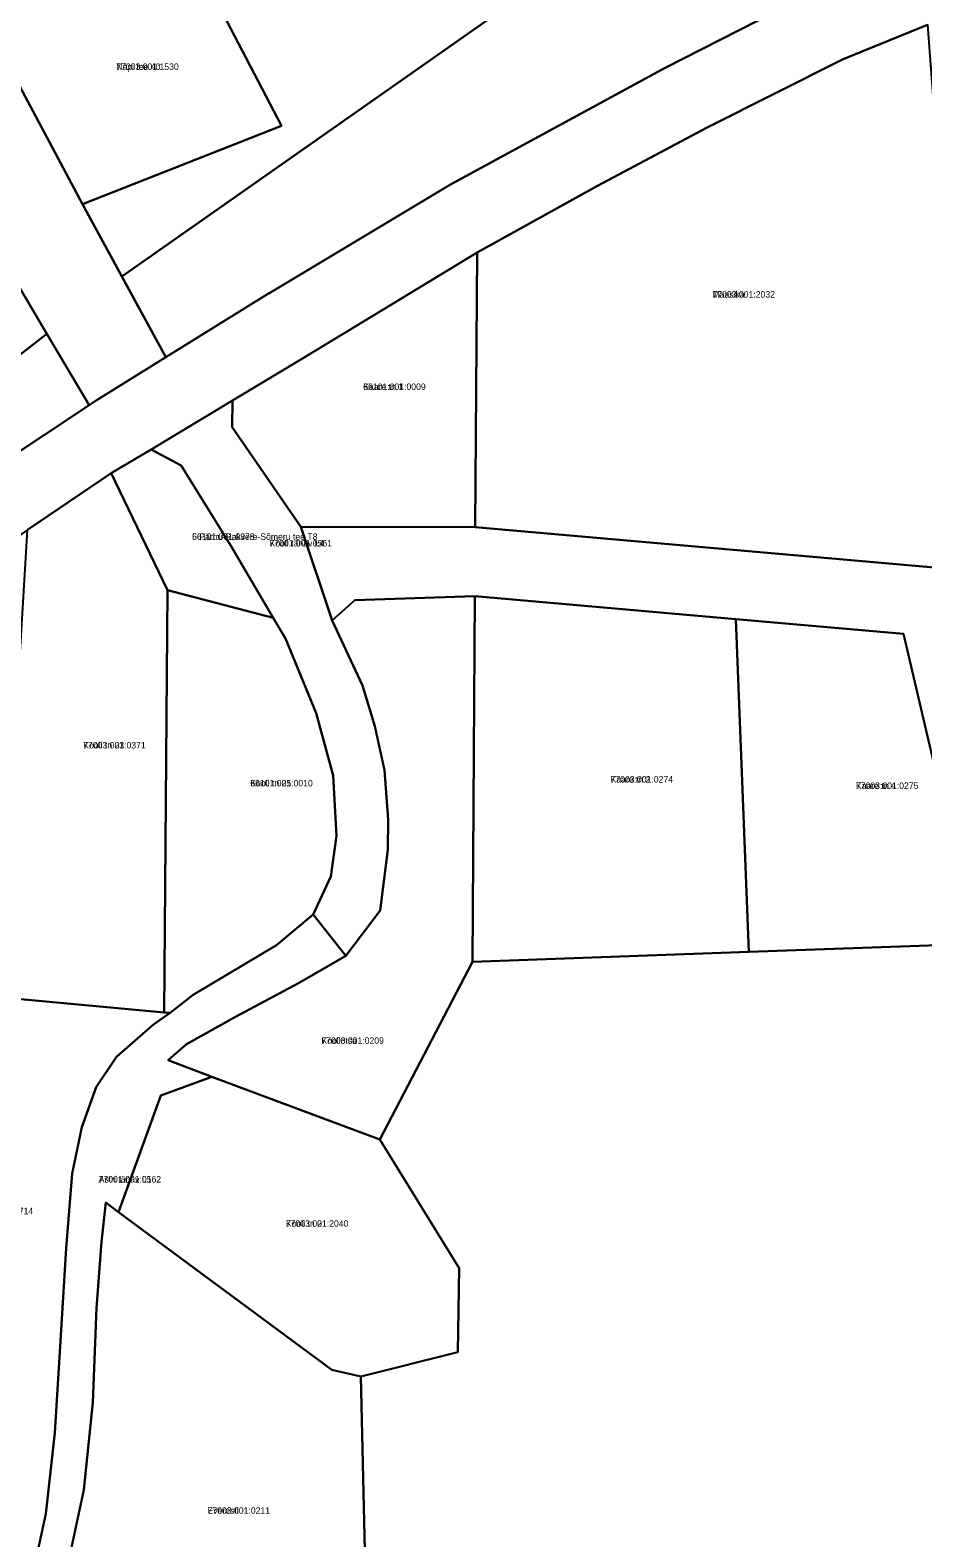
# Model space of a CAD drawing. Extents: x 623860 to 651189, y 6568632 to 6595301.
# Drawn here: x 637482.8 to 637690, y 6582786.6 to 6583136.7 of the extents above; entities that cross this region are included whole.
import ezdxf

# ---------------------------------------------------------------- set-up
doc = ezdxf.new("R2010")
doc.units = 0
for name, color, linetype in [('L_AADRESS', 7, 'Continuous'), ('PIIR', 7, 'Continuous'), ('TUNNUS', 7, 'Continuous')]:
    doc.layers.add(name, color=color, linetype=linetype)

msp = doc.modelspace()

# ---------------------------------------------------------------- linework, layer by layer
at = {"layer": 'PIIR'}
for points in [[(637664.58, 6583145.57), (637630.24, 6583127.99), (637580.36, 6583100.85), (637538.2, 6583075.58), (637538.14, 6583075.54), (637514.33, 6583060.75), (637504.07, 6583079.52), (637681.36, 6583204.02), (637593.23, 6583199.04), (637592.53, 6583223.86), (637698.28, 6583229.62), (637708.99, 6583228.52), (637719.35, 6583225.99), (637729.32, 6583220.64), (637736.52, 6583214.45), (637741.35, 6583206.97), (637744.44, 6583198.83), (637744.49, 6583193.71), (637742.02, 6583189.18), (637738.27, 6583184.7), (637729.25, 6583178.18), (637682.67, 6583156.5), (637683.54, 6583154.29)], [(637504.07, 6583079.52), (637494.93, 6583096.33), (637541.17, 6583114.55), (637519.37, 6583156.38), (637496.48, 6583201.94), (637442.21, 6583199.87), (637440.75, 6583215.97), (637460.63, 6583216.53), (637554.82, 6583221.8), (637592.53, 6583223.86), (637593.23, 6583199.04), (637681.36, 6583204.02)], [(637415.47, 6583190.09), (637442.21, 6583199.87), (637446.78, 6583186.97), (637464.42, 6583153.71), (637494.93, 6583096.33), (637514.33, 6583060.75), (637498.15, 6583050.71), (637496.53, 6583049.6), (637486.68, 6583066.22), (637474.63, 6583086.57), (637465.77, 6583101.63), (637440.2, 6583145.49)], [(637494.93, 6583096.33), (637464.42, 6583153.71), (637519.37, 6583156.38), (637541.17, 6583114.55)], [(637586.14, 6583021.27), (637586.6, 6583085.07), (637614.51, 6583100.6), (637639.95, 6583114.09), (637671.56, 6583130), (637691.14, 6583138), (637700.65, 6583011.25)], [(637283.7, 6583004.84), (637286.66, 6583019.42), (637332.27, 6583011.79), (637366.88, 6582993.12), (637372.51, 6582990.04), (637411.98, 6583044.83), (637474.63, 6583086.57), (637486.68, 6583066.22), (637356.1, 6582964.62), (637334.62, 6582977.66), (637303.57, 6582990.13), (637304.57, 6582996.04), (637305.76, 6583003.28), (637300.89, 6583004.14), (637299.66, 6582996.82)], [(637545.66, 6583021.35), (637529.73, 6583044.54), (637529.75, 6583050.69), (637546.83, 6583060.93), (637586.6, 6583085.07), (637586.14, 6583021.27)], [(637443.63, 6583014.57), (637416.27, 6582994.48), (637415.68, 6582995.29), (637398.39, 6582982.59), (637364.92, 6582959.27), (637356.1, 6582964.62), (637486.68, 6583066.22), (637496.53, 6583049.6)], [(637510.87, 6583039.36), (637529.75, 6583050.69), (637529.73, 6583044.54), (637545.66, 6583021.35), (637552.9, 6582999.61), (637559.98, 6582984.54), (637562.86, 6582975.09), (637565.09, 6582964.86), (637565.89, 6582953.41), (637565.83, 6582946.36), (637564.04, 6582932.3), (637556.08, 6582921.78), (637548.54, 6582931.33), (637552.59, 6582940.18), (637553.91, 6582949.59), (637553.15, 6582963.61), (637549.21, 6582978.1), (637542.05, 6582995.42), (637539.21, 6583000.27), (637529.35, 6583017.15), (637517.88, 6583035.6)], [(637529.35, 6583017.15), (637539.21, 6583000.27), (637514.71, 6583006.64), (637501.6, 6583033.85), (637510.87, 6583039.36), (637517.88, 6583035.6)], [(637475.56, 6582912.14), (637476.42, 6582924.25), (637481.01, 6583001.28), (637482.17, 6583020.72), (637501.6, 6583033.85), (637514.71, 6583006.64), (637513.93, 6582908.6)], [(637545.66, 6583021.35), (637586.14, 6583021.27), (637700.65, 6583011.25), (637701.56, 6582999.05), (637709.9, 6582962.87), (637728.05, 6582884.82), (637729.92, 6582876.27), (637737.18, 6582842.17), (637722.1, 6582837.44), (637702.43, 6582924.56), (637685.56, 6582996.5), (637646.59, 6582999.93), (637586.04, 6583005.25), (637558.21, 6583004.35), (637552.9, 6582999.61)], [(637513.93, 6582908.6), (637514.71, 6583006.64), (637539.21, 6583000.27), (637542.05, 6582995.42), (637549.21, 6582978.1), (637553.15, 6582963.61), (637553.91, 6582949.59), (637552.59, 6582940.18), (637548.54, 6582931.33), (637540.03, 6582924.21), (637520.63, 6582912.68), (637515.28, 6582908.47)], [(637552.9, 6582999.61), (637558.21, 6583004.35), (637586.04, 6583005.25), (637585.49, 6582920.34), (637563.95, 6582879.08), (637525.01, 6582893.66), (637514.83, 6582897.48), (637519.09, 6582901.21), (637530.46, 6582907.59), (637545.14, 6582915.37), (637556.08, 6582921.78), (637564.04, 6582932.3), (637565.83, 6582946.36), (637565.89, 6582953.41), (637565.09, 6582964.86), (637562.86, 6582975.09), (637559.98, 6582984.54)], [(637586.04, 6583005.25), (637646.59, 6582999.93), (637649.61, 6582922.64), (637585.49, 6582920.34)], [(637646.59, 6582999.93), (637685.56, 6582996.5), (637702.43, 6582924.56), (637649.61, 6582922.64)], [(637585.49, 6582920.34), (637649.61, 6582922.64), (637702.43, 6582924.56), (637722.1, 6582837.44), (637718.93, 6582825.63), (637692.97, 6582815.36), (637703.58, 6582810.33), (637719.47, 6582815.5), (637737.42, 6582679.54), (637683.24, 6582617.74), (637563.99, 6582631.43), (637562.04, 6582716.12), (637559.54, 6582824.01), (637582.06, 6582829.68), (637582.39, 6582849.21), (637563.95, 6582879.08)], [(637513.14, 6582889.28), (637525.01, 6582893.66), (637563.95, 6582879.08), (637582.39, 6582849.21), (637582.06, 6582829.68), (637559.54, 6582824.01), (637552.84, 6582825.57), (637503.31, 6582862.25)], [(637500.35, 6582864.44), (637503.31, 6582862.25), (637552.84, 6582825.57), (637559.54, 6582824.01), (637562.04, 6582716.12), (637487.65, 6582757.73), (637485.95, 6582758.7), (637489.72, 6582771.62), (637495.31, 6582797.69), (637497.33, 6582818), (637498.24, 6582839.95), (637499.41, 6582855.35)]]:
    msp.add_lwpolyline(points, close=True, dxfattribs=at)
for points in [[(637122.09, 6582748.11), (637238.84, 6582855.91), (637317, 6582923.08), (637364.92, 6582959.27), (637398.39, 6582982.59), (637415.68, 6582995.29), (637416.27, 6582994.48), (637443.63, 6583014.57), (637496.53, 6583049.6), (637498.15, 6583050.71), (637514.33, 6583060.75), (637538.14, 6583075.54), (637538.2, 6583075.58), (637580.36, 6583100.85), (637630.24, 6583127.99), (637664.58, 6583145.57)], [(637691.14, 6583138), (637671.56, 6583130), (637639.95, 6583114.09), (637614.51, 6583100.6), (637586.6, 6583085.07), (637546.83, 6583060.93), (637529.75, 6583050.69), (637510.87, 6583039.36), (637501.6, 6583033.85), (637482.17, 6583020.72), (637410.06, 6582969.65), (637410.66, 6582968.86), (637376.03, 6582943.86), (637329.23, 6582908.31), (637310.68, 6582893), (637283.74, 6582870.09), (637253.45, 6582843.67), (637220.82, 6582814.02), (637135.37, 6582734)], [(637483.46, 6582778.25), (637486.48, 6582792.15), (637488.57, 6582810.96), (637489.97, 6582833.59), (637491.16, 6582853.84), (637492.54, 6582871.2), (637494.84, 6582881.97), (637498.17, 6582891.26), (637502.82, 6582898.26), (637511.42, 6582905.81), (637515.28, 6582908.47), (637520.63, 6582912.68), (637540.03, 6582924.21), (637548.54, 6582931.33), (637556.08, 6582921.78), (637545.14, 6582915.37), (637530.46, 6582907.59), (637519.09, 6582901.21), (637514.83, 6582897.48), (637525.01, 6582893.66), (637513.14, 6582889.28), (637503.31, 6582862.25), (637500.35, 6582864.44), (637499.41, 6582855.35), (637498.24, 6582839.95), (637497.33, 6582818), (637495.31, 6582797.69), (637489.72, 6582771.62)], [(637475.56, 6582912.14), (637513.93, 6582908.6), (637515.28, 6582908.47), (637511.42, 6582905.81), (637502.82, 6582898.26), (637498.17, 6582891.26), (637494.84, 6582881.97), (637492.54, 6582871.2), (637491.16, 6582853.84), (637489.97, 6582833.59), (637488.57, 6582810.96), (637486.48, 6582792.15), (637483.46, 6582778.25)]]:
    msp.add_lwpolyline(points, dxfattribs=at)

# ---------------------------------------------------------------- texts
at = {"layer": 'L_AADRESS'}
for s, p in [('Näpi tee 40', (637502.8, 6583127.5)), ('Maasika', (637641.21, 6583074.62)), ('Kaare tn 1', (637560.13, 6583053.17)), ('5 Pärnu-Rakvere-Sõmeru tee T8', (637520.41, 6583018.35)), ('Kooli tänav L4', (637538.38, 6583016.82)), ('Kooli tn 23', (637495.14, 6582969.91)), ('Kooli tn 25', (637533.92, 6582961.11)), ('Kaare tn 2', (637617.55, 6582961.99)), ('Kaare tn 4', (637674.51, 6582960.51)), ('Kooliotsa', (637550.43, 6582901.31)), ('Astri tänav L1', (637498.71, 6582869.1)), ('Kooli tn 21', (637542.18, 6582858.84)), ('Everesti', (637524, 6582792.17))]:
    msp.add_text(s, height=1.5, dxfattribs=at).set_placement(p)
at = {"layer": 'TUNNUS'}
for s, p in [('77003:001:1530', (637502.8, 6583127.5)), ('77003:001:2032', (637641.21, 6583074.62)), ('66101:001:0009', (637560.13, 6583053.17)), ('66101:001:0378', (637520.41, 6583018.35)), ('77001:001:0561', (637538.38, 6583016.82)), ('77003:001:0371', (637495.14, 6582969.91)), ('66101:001:0010', (637533.92, 6582961.11)), ('77003:001:0274', (637617.55, 6582961.99)), ('77003:001:0275', (637674.51, 6582960.51)), ('77003:001:0209', (637550.43, 6582901.31)), ('77001:001:0562', (637498.71, 6582869.1)), ('77001:001:0714', (637469.02, 6582861.72)), ('77003:001:2040', (637542.18, 6582858.84)), ('77003:001:0211', (637524, 6582792.17))]:
    msp.add_text(s, height=1.5, dxfattribs=at).set_placement(p)

doc.saveas('drawing.dxf')
